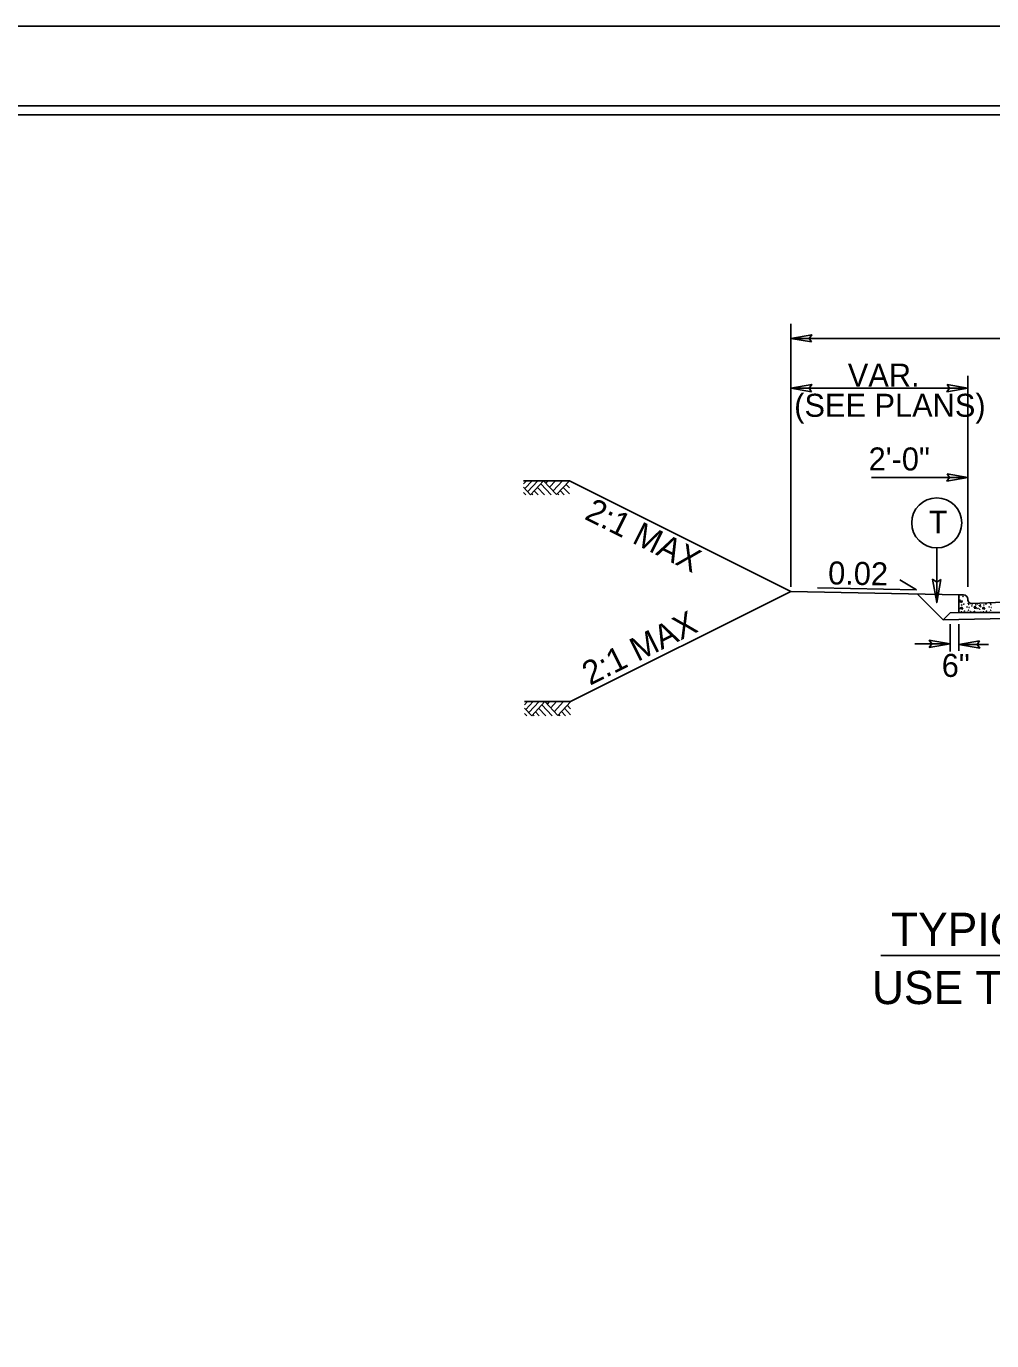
# Model space of a CAD drawing. Extents: x 1904401 to 1905163, y 193929 to 194736.
# Drawn here: x 1904829.1 to 1904883.7, y 194169.2 to 194243.4 of the extents above; entities that cross this region are included whole.
import ezdxf

# ---------------------------------------------------------------- set-up
doc = ezdxf.new("R2010")
doc.units = 0
for name, color, linetype in [('Old_Level_1', 7, 'Continuous'), ('Old_Level_11', 7, 'Continuous'), ('Old_Level_20', 7, 'Continuous'), ('Prop Dimension Text', 7, 'Continuous'), ('Prop Lane Arrow CELL', 7, 'Continuous'), ('Sheet Cutting Line CELL', 7, 'Continuous'), ('Sheet Plot Border Inside CELL', 7, 'Continuous'), ('Sheet Plot Border Outside CELL', 7, 'Continuous'), ('Sheet Typical CELL', 7, 'Continuous'), ('Typical Arrow Superelevation CELL', 7, 'Continuous'), ('Typical Berm CELL', 7, 'Continuous'), ('Typical Curb CELL', 7, 'Continuous'), ('Typical Hinge Slope Arterial CELL', 7, 'Continuous'), ('Typical Pavement Slope CELL', 7, 'Continuous'), ('Typical Terminator CELL', 7, 'Continuous')]:
    doc.layers.add(name, color=color, linetype=linetype)

msp = doc.modelspace()

# ---------------------------------------------------------------- linework, layer by layer
at = {"layer": 'Old_Level_1'}
for p, q in [((1904872.299, 194225.805), (1904935.799, 194225.805)), ((1904872.299, 194222.993), (1904882.299, 194222.993)), ((1904857.349, 194217.761), (1904857.179, 194217.578)), ((1904857.669, 194217.761), (1904857.255, 194217.317)), ((1904858.002, 194217.761), (1904857.422, 194217.138)), ((1904858.324, 194217.76), (1904857.583, 194216.964)), ((1904859.055, 194216.974), (1904858.324, 194217.76)), ((1904858.588, 194217.761), (1904858.455, 194217.618)), ((1904858.99, 194217.761), (1904858.657, 194217.402)), ((1904859.388, 194217.761), (1904858.855, 194217.188)), ((1904859.779, 194217.753), (1904859.055, 194216.974)), ((1904876.852, 194217.947), (1904882.299, 194217.947)), ((1904857.583, 194216.964), (1904857.179, 194217.399)), ((1904857.313, 194216.956), (1904857.179, 194217.099)), ((1904857.714, 194216.956), (1904857.645, 194217.03)), ((1904858.009, 194216.956), (1904857.792, 194217.189)), ((1904858.375, 194216.956), (1904857.975, 194217.385)), ((1904858.745, 194216.956), (1904858.159, 194217.584)), ((1904859.18, 194216.956), (1904859.109, 194217.032)), ((1904859.491, 194216.956), (1904859.264, 194217.199)), ((1904859.779, 194217.019), (1904859.437, 194217.385)), ((1904859.779, 194217.352), (1904859.593, 194217.552)), ((1904857.416, 194205.275), (1904857.246, 194205.092)), ((1904857.736, 194205.275), (1904857.322, 194204.831)), ((1904858.069, 194205.275), (1904857.489, 194204.652)), ((1904858.391, 194205.274), (1904857.65, 194204.478)), ((1904858.812, 194204.47), (1904858.226, 194205.098)), ((1904859.122, 194204.488), (1904858.391, 194205.274)), ((1904858.655, 194205.275), (1904858.522, 194205.132)), ((1904859.057, 194205.275), (1904858.724, 194204.916)), ((1904859.455, 194205.275), (1904858.922, 194204.702)), ((1904859.846, 194205.267), (1904859.122, 194204.488)), ((1904859.846, 194204.866), (1904859.66, 194205.066)), ((1904857.65, 194204.478), (1904857.246, 194204.913)), ((1904857.38, 194204.47), (1904857.246, 194204.613)), ((1904857.781, 194204.47), (1904857.712, 194204.544)), ((1904858.076, 194204.47), (1904857.859, 194204.703)), ((1904858.442, 194204.47), (1904858.042, 194204.899)), ((1904859.247, 194204.47), (1904859.176, 194204.546)), ((1904859.558, 194204.47), (1904859.331, 194204.713)), ((1904859.846, 194204.533), (1904859.504, 194204.899)), ((1904877.386, 194190.926), (1904929.779, 194190.926))]:
    msp.add_line(p, q, dxfattribs=at)
for points in [[(1904859.779, 194217.761), (1904857.179, 194217.761)], [(1904859.846, 194205.275), (1904857.246, 194205.275)]]:
    msp.add_lwpolyline(points, dxfattribs=at)
at = {"layer": 'Old_Level_11'}
msp.add_line((1904880.545, 194213.965), (1904880.545, 194210.874), dxfattribs=at)
msp.add_lwpolyline([(1904880.77, 194212.184), (1904880.545, 194210.874), (1904880.312, 194212.191), (1904880.545, 194212.023)], close=True, dxfattribs=at)
msp.add_circle((1904880.545, 194215.379), 1.414, dxfattribs=at)
at = {"layer": 'Prop Dimension Text'}
for p, q in [((1904872.299, 194226.633), (1904872.299, 194211.767)), ((1904882.299, 194223.686), (1904882.299, 194211.767))]:
    msp.add_line(p, q, dxfattribs=at)
at = {"layer": 'Prop Lane Arrow CELL'}
for p, q in [((1904881.299, 194209.653), (1904881.299, 194208.114)), ((1904881.799, 194209.652), (1904881.799, 194208.154)), ((1904881.299, 194208.536), (1904879.309, 194208.536)), ((1904883.471, 194208.508), (1904881.799, 194208.508))]:
    msp.add_line(p, q, dxfattribs=at)
at = {"layer": 'Sheet Cutting Line CELL'}
msp.add_line((1905047.492, 194243.443), (1904710.692, 194243.443), dxfattribs=at)
at = {"layer": 'Sheet Plot Border Inside CELL'}
msp.add_lwpolyline([(1905046.592, 194238.953), (1904713.292, 194238.953), (1904713.292, 194027.933), (1905046.592, 194027.933)], close=True, dxfattribs=at)
at = {"layer": 'Sheet Plot Border Outside CELL'}
msp.add_lwpolyline([(1905047.492, 194243.443), (1904710.692, 194243.443), (1904710.692, 194023.443), (1905047.492, 194023.443)], close=True, dxfattribs=at)
at = {"layer": 'Sheet Typical CELL'}
msp.add_lwpolyline([(1905044.092, 194238.443), (1904744.092, 194238.443), (1904744.092, 194028.443), (1905044.092, 194028.443)], close=True, dxfattribs=at)
at = {"layer": 'Typical Arrow Superelevation CELL'}
for q in [(1904878.466, 194212.166), (1904873.812, 194211.71)]:
    msp.add_line((1904879.405, 194211.598), q, dxfattribs=at)
at = {"layer": 'Typical Berm CELL'}
msp.add_line((1904872.299, 194211.501), (1904881.799, 194211.303), dxfattribs=at)
at = {"layer": 'Typical Curb CELL'}
for p, q in [((1904881.799, 194210.303), (1904881.799, 194211.303)), ((1904881.799, 194211.303), (1904882.06, 194211.303)), ((1904882.299, 194211.053), (1904882.299, 194211.064)), ((1904881.799, 194210.303), (1904884.299, 194210.303)), ((1904881.836, 194210.925), (1904881.99, 194210.97)), ((1904881.973, 194210.879), (1904881.836, 194210.925)), ((1904881.962, 194210.606), (1904881.859, 194210.531)), ((1904881.859, 194210.531), (1904882.024, 194210.492)), ((1904882.024, 194210.492), (1904881.962, 194210.606)), ((1904881.99, 194210.97), (1904881.973, 194210.879)), ((1904884.299, 194210.887), (1904882.549, 194210.814)), ((1904882.703, 194210.663), (1904882.669, 194210.549)), ((1904882.669, 194210.549), (1904882.789, 194210.543)), ((1904882.789, 194210.543), (1904882.703, 194210.663)), ((1904883.211, 194210.606), (1904883.107, 194210.531)), ((1904883.107, 194210.531), (1904883.273, 194210.492)), ((1904883.273, 194210.492), (1904883.211, 194210.606))]:
    msp.add_line(p, q, dxfattribs=at)
for centre in [(1904881.813, 194211.193), (1904881.864, 194211.011), (1904882.03, 194211.227), (1904881.944, 194210.349), (1904881.961, 194210.737), (1904882.081, 194210.788), (1904882.115, 194210.389), (1904882.258, 194210.623), (1904882.292, 194210.326), (1904882.338, 194210.816), (1904882.349, 194210.441), (1904882.355, 194210.766), (1904882.384, 194210.595), (1904882.464, 194210.355), (1904882.532, 194210.68), (1904882.56, 194210.782), (1904882.669, 194210.378), (1904882.755, 194210.743), (1904882.829, 194210.309), (1904882.852, 194210.797), (1904882.88, 194210.543), (1904882.96, 194210.703), (1904882.976, 194210.498), (1904883.016, 194210.737), (1904883.033, 194210.64), (1904883.039, 194210.332), (1904883.193, 194210.349), (1904883.21, 194210.737), (1904883.33, 194210.788), (1904883.364, 194210.389), (1904883.507, 194210.623), (1904883.541, 194210.326), (1904883.587, 194210.816), (1904883.598, 194210.441), (1904883.604, 194210.766), (1904883.633, 194210.595)]:
    msp.add_circle(centre, 0.00802, dxfattribs=at)
for centre, start, end in [((1904882.06, 194211.064), 0, 90), ((1904882.539, 194211.053), 180, 272.38446)]:
    msp.add_arc(centre, 0.24, start, end, dxfattribs=at)
at = {"layer": 'Typical Hinge Slope Arterial CELL'}
for p in [(1904859.779, 194217.761), (1904859.846, 194205.275)]:
    msp.add_line(p, (1904872.299, 194211.501), dxfattribs=at)
at = {"layer": 'Typical Pavement Slope CELL'}
for p, q in [((1904880.908, 194209.902), (1904879.458, 194211.352)), ((1904880.908, 194209.902), (1904904.067, 194210.365)), ((1904880.908, 194209.902), (1904881.299, 194210.293)), ((1904881.299, 194210.293), (1904881.799, 194210.303))]:
    msp.add_line(p, q, dxfattribs=at)
at = {"layer": 'Typical Terminator CELL'}
for points in [[(1904873.471, 194225.604), (1904872.299, 194225.805), (1904873.477, 194226.014), (1904873.327, 194225.805)], [(1904873.471, 194222.791), (1904872.299, 194222.993), (1904873.477, 194223.201), (1904873.327, 194222.993)], [(1904881.127, 194223.195), (1904882.299, 194222.993), (1904881.121, 194222.785), (1904881.27, 194222.993)], [(1904881.127, 194218.149), (1904882.299, 194217.947), (1904881.121, 194217.738), (1904881.27, 194217.947)], [(1904880.128, 194208.334), (1904881.299, 194208.536), (1904880.121, 194208.744), (1904880.271, 194208.536)], [(1904882.971, 194208.71), (1904881.799, 194208.508), (1904882.977, 194208.3), (1904882.828, 194208.508)]]:
    msp.add_lwpolyline(points, close=True, dxfattribs=at)

# ---------------------------------------------------------------- texts
at = {"layer": 'Old_Level_1'}
for s, height, p in [('VAR.', 1.3, (1904875.519, 194223.077)), ('(SEE PLANS)', 1.3, (1904872.489, 194221.373)), ('2\'-0" ', 1.3, (1904876.697, 194218.34)), ('6" ', 1.3, (1904880.83, 194206.672)), ('TYPICAL SECTION NO. 15 (INTERSECTIONS)', 1.875, (1904877.963, 194191.47))]:
    msp.add_text(s, height=height, dxfattribs=at).set_placement(p)
at = {"layer": 'Old_Level_20'}
msp.add_text('T', height=1.279, dxfattribs=at).set_placement((1904880.109, 194214.782))
at = {"layer": 'Prop Dimension Text'}
msp.add_text('0.02', height=1.3, rotation=358.8538, dxfattribs=at).set_placement((1904874.398, 194211.906))
at = {"layer": 'Prop Lane Arrow CELL'}
msp.add_text('USE TYPICAL SECTION NO. 15', height=1.875, dxfattribs=at).set_placement((1904876.883, 194188.18))
at = {"layer": 'Typical Hinge Slope Arterial CELL'}
for rotation, p in [(333.43495, (1904860.571, 194215.623)), (26.56505, (1904860.942, 194206.164))]:
    msp.add_text('2:1 MAX', height=1.35, rotation=rotation, dxfattribs=at).set_placement(p)

doc.saveas('drawing.dxf')
